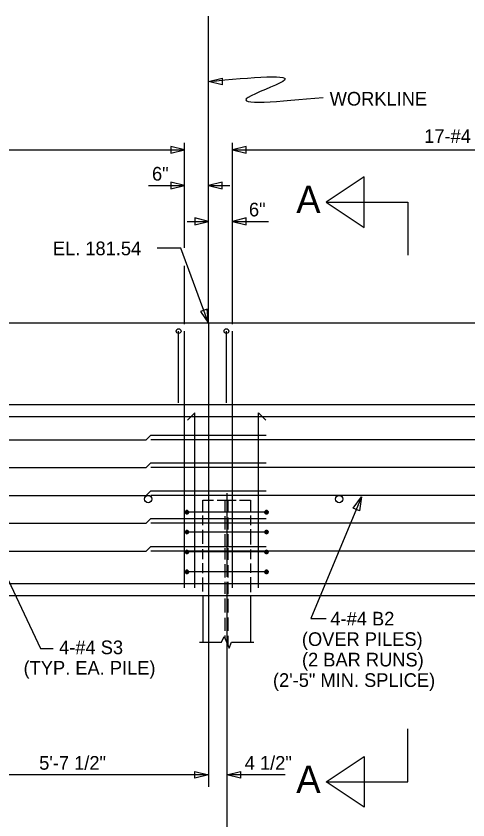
# Model space of a CAD drawing. Extents: x -41 to 191, y -168 to 6.
# Drawn here: x 28.81 to 38.27, y -40.55 to -23.72 of the extents above; entities that cross this region are included whole.
import ezdxf

# ---------------------------------------------------------------- set-up
doc = ezdxf.new("R2010")
doc.units = 0
for name, color, linetype in [('Arrowhead Terminators CELL', 7, 'Continuous'), ('Dimension Lines', 7, 'Continuous'), ('Mis -L- Lines', 7, 'Continuous'), ('Mis Object Lines', 7, 'Continuous'), ('Mis Object Lines Hidden', 7, 'Continuous'), ('Rebar Lines', 7, 'Continuous'), ('Rebar Lines CELL', 7, 'Continuous'), ('Text', 7, 'Continuous'), ('Title Text', 7, 'Continuous')]:
    doc.layers.add(name, color=color, linetype=linetype)

msp = doc.modelspace()

# ---------------------------------------------------------------- linework, layer by layer
at = {"layer": 'Arrowhead Terminators CELL'}
for points in [[(32.837, -25.09), (33.124, -25.018), (33.124, -25.161)], [(32.337, -26.52), (32.051, -26.448), (32.051, -26.591)], [(33.337, -26.52), (33.624, -26.591), (33.624, -26.448)], [(35.301, -27.616), (36.095, -28.145), (36.095, -27.087)], [(32.337, -27.27), (32.051, -27.198), (32.051, -27.341)], [(32.837, -27.27), (33.124, -27.341), (33.124, -27.198)], [(32.837, -28.02), (32.551, -27.948), (32.551, -28.091)], [(33.337, -28.02), (33.624, -28.091), (33.624, -27.948)], [(32.837, -30.152), (32.806, -29.858), (32.671, -29.908)], [(36.041, -33.79), (35.997, -34.082), (35.865, -34.027)], [(35.301, -39.757), (36.095, -39.228), (36.095, -40.286)], [(32.837, -39.61), (32.551, -39.681), (32.551, -39.538)], [(33.219, -39.61), (33.505, -39.538), (33.505, -39.681)]]:
    msp.add_lwpolyline(points, close=True, dxfattribs=at)
at = {"layer": 'Dimension Lines'}
for p, q in [((32.337, -28.571), (32.337, -26.377)), ((33.337, -30.175), (33.337, -26.377)), ((16.318, -26.52), (32.337, -26.52)), ((33.337, -26.52), (49.41, -26.52)), ((31.583, -27.27), (32.337, -27.27)), ((32.837, -27.27), (33.283, -27.27)), ((32.392, -28.02), (32.837, -28.02)), ((33.337, -28.02), (34.092, -28.02)), ((32.337, -30.175), (32.337, -28.947)), ((28.46, -35.153), (29.319, -36.963)), ((33.219, -35.86), (33.219, -42.157)), ((29.319, -36.963), (29.587, -36.963)), ((32.837, -39.61), (27.219, -39.61)), ((34.446, -39.61), (33.219, -39.61))]:
    msp.add_line(p, q, dxfattribs=at)
for points in [[(35.301, -27.616), (37.013, -27.616), (37.013, -28.727)], [(32.837, -30.152), (32.26, -28.581), (31.76, -28.581)], [(36.041, -33.79), (34.981, -36.334), (35.298, -36.334)], [(35.301, -39.757), (37.013, -39.757), (37.013, -38.646)]]:
    msp.add_lwpolyline(points, dxfattribs=at)
msp.add_spline([(32.837, -25.09), (34.392, -25.09), (33.667, -25.423), (35.236, -25.423)], degree=3, dxfattribs=at)
at = {"layer": 'Mis -L- Lines'}
for q in [(32.837, -23.72), (32.837, -39.86)]:
    msp.add_line((32.837, -30.152), q, dxfattribs=at)
at = {"layer": 'Mis Object Lines'}
for p, q in [((43.116, -30.152), (16.026, -30.152)), ((47.445, -35.86), (12.601, -35.86))]:
    msp.add_line(p, q, dxfattribs=at)
at = {"layer": 'Mis Object Lines Hidden'}
msp.add_line((49.619, -31.86), (12.601, -31.86), dxfattribs=at)
at = {"layer": 'Rebar Lines'}
for p, q in [((32.212, -31.818), (32.212, -30.318)), ((32.337, -35.693), (32.337, -30.318)), ((33.212, -31.818), (33.212, -30.318)), ((33.337, -35.693), (33.337, -30.318)), ((53.096, -32.111), (14.053, -32.111)), ((32.552, -32.027), (32.399, -32.18)), ((32.552, -35.693), (32.552, -32.027)), ((33.886, -35.693), (33.886, -32.027)), ((33.886, -32.027), (34.039, -32.18)), ((13.513, -32.591), (31.532, -32.591)), ((31.532, -32.591), (31.629, -32.494)), ((31.629, -32.494), (34.046, -32.494)), ((53.554, -32.591), (31.629, -32.591)), ((31.532, -33.174), (31.629, -33.077)), ((31.629, -33.077), (34.046, -33.077)), ((13.513, -33.174), (31.532, -33.174)), ((53.554, -33.174), (31.629, -33.174)), ((31.532, -33.757), (31.629, -33.661)), ((31.629, -33.661), (34.046, -33.661)), ((13.513, -33.757), (31.532, -33.757)), ((53.554, -33.757), (31.629, -33.757)), ((33.219, -33.709), (33.219, -35.465)), ((33.187, -34.103), (33.187, -33.86)), ((33.25, -34.108), (33.25, -33.86)), ((13.513, -34.34), (31.532, -34.34)), ((31.532, -34.34), (31.629, -34.244)), ((31.629, -34.244), (34.046, -34.244)), ((53.554, -34.34), (31.629, -34.34)), ((33.187, -34.474), (33.187, -34.196)), ((33.25, -34.474), (33.25, -34.219)), ((33.187, -34.817), (33.187, -34.567)), ((33.25, -34.829), (33.25, -34.567)), ((31.532, -34.924), (31.629, -34.827)), ((31.629, -34.827), (34.046, -34.827)), ((13.513, -34.924), (31.532, -34.924)), ((53.554, -34.924), (31.629, -34.924)), ((33.187, -35.103), (33.187, -34.86)), ((33.25, -35.108), (33.25, -34.86)), ((33.187, -35.474), (33.187, -35.196)), ((33.25, -35.474), (33.25, -35.219)), ((53.096, -35.61), (13.96, -35.61)), ((33.187, -35.817), (33.187, -35.567)), ((33.219, -35.57), (33.219, -35.86)), ((33.25, -35.829), (33.25, -35.567)), ((32.718, -35.877), (32.718, -36.829)), ((33.187, -36.212), (33.187, -35.916)), ((33.219, -35.93), (33.219, -37.136)), ((33.25, -36.212), (33.25, -35.922)), ((33.72, -35.877), (33.72, -36.829)), ((33.187, -36.595), (33.187, -36.322)), ((33.25, -36.595), (33.25, -36.317)), ((33.187, -36.763), (33.187, -36.689)), ((33.25, -36.913), (33.25, -36.7))]:
    msp.add_line(p, q, dxfattribs=at)
for points in [[(32.718, -34.094), (32.718, -33.86), (32.941, -33.86)], [(33.017, -33.86), (33.416, -33.86)], [(33.486, -33.86), (33.718, -33.86), (33.718, -34.106)], [(32.718, -34.384), (32.718, -34.176)], [(33.718, -34.182), (33.718, -34.381)], [(32.718, -34.771), (32.718, -34.48)], [(33.718, -34.467), (33.718, -34.787)], [(32.718, -35.094), (32.718, -34.886)], [(33.718, -34.892), (33.718, -35.091)], [(32.718, -35.384), (32.718, -35.176)], [(33.718, -35.182), (33.718, -35.381)], [(32.718, -35.771), (32.718, -35.48)], [(33.718, -35.467), (33.718, -35.787)], [(32.649, -36.829), (33.111, -36.829), (33.165, -36.71), (33.267, -36.954), (33.319, -36.829), (33.786, -36.829)]]:
    msp.add_lwpolyline(points, dxfattribs=at)
for centre in [(32.212, -30.318), (33.212, -30.318)]:
    msp.add_circle(centre, 0.0495, dxfattribs=at)
at = {"layer": 'Rebar Lines CELL'}
for p, q in [((34.052, -34.11), (32.386, -34.11)), ((34.052, -34.527), (32.386, -34.527)), ((34.052, -34.943), (32.386, -34.943)), ((34.052, -35.36), (32.386, -35.36))]:
    msp.add_line(p, q, dxfattribs=at)
for points in [[(32.386, -34.075), (32.372, -34.077), (32.361, -34.085), (32.353, -34.096), (32.35, -34.11), (32.353, -34.123), (32.361, -34.135), (32.372, -34.142), (32.386, -34.145), (32.399, -34.142), (32.41, -34.135), (32.418, -34.123), (32.421, -34.11), (32.418, -34.096), (32.411, -34.085), (32.399, -34.077), (32.386, -34.075), (32.386, -34.11), (32.386, -34.145), (32.372, -34.142), (32.386, -34.11), (32.361, -34.135), (32.353, -34.123), (32.386, -34.11), (32.35, -34.11), (32.353, -34.096), (32.386, -34.11), (32.361, -34.085), (32.372, -34.077), (32.386, -34.11), (32.399, -34.077), (32.411, -34.085), (32.386, -34.11), (32.418, -34.096), (32.421, -34.11), (32.386, -34.11), (32.418, -34.123), (32.41, -34.135), (32.386, -34.11), (32.399, -34.142)], [(34.052, -34.075), (34.039, -34.077), (34.027, -34.085), (34.02, -34.096), (34.017, -34.11), (34.02, -34.123), (34.027, -34.135), (34.039, -34.142), (34.052, -34.145), (34.066, -34.142), (34.077, -34.135), (34.085, -34.123), (34.088, -34.11), (34.085, -34.096), (34.077, -34.085), (34.066, -34.077), (34.052, -34.075), (34.052, -34.11), (34.052, -34.145), (34.039, -34.142), (34.052, -34.11), (34.027, -34.135), (34.02, -34.123), (34.052, -34.11), (34.017, -34.11), (34.02, -34.096), (34.052, -34.11), (34.027, -34.085), (34.039, -34.077), (34.052, -34.11), (34.066, -34.077), (34.077, -34.085), (34.052, -34.11), (34.085, -34.096), (34.088, -34.11), (34.052, -34.11), (34.085, -34.123), (34.077, -34.135), (34.052, -34.11), (34.066, -34.142)], [(32.386, -34.491), (32.372, -34.494), (32.361, -34.502), (32.353, -34.513), (32.35, -34.527), (32.353, -34.54), (32.361, -34.551), (32.372, -34.559), (32.386, -34.562), (32.399, -34.559), (32.41, -34.551), (32.418, -34.54), (32.421, -34.527), (32.418, -34.513), (32.411, -34.502), (32.399, -34.494), (32.386, -34.491), (32.386, -34.527), (32.386, -34.562), (32.372, -34.559), (32.386, -34.527), (32.361, -34.551), (32.353, -34.54), (32.386, -34.527), (32.35, -34.527), (32.353, -34.513), (32.386, -34.527), (32.361, -34.502), (32.372, -34.494), (32.386, -34.527), (32.399, -34.494), (32.411, -34.502), (32.386, -34.527), (32.418, -34.513), (32.421, -34.527), (32.386, -34.527), (32.418, -34.54), (32.41, -34.551), (32.386, -34.527), (32.399, -34.559)], [(34.052, -34.491), (34.039, -34.494), (34.027, -34.502), (34.02, -34.513), (34.017, -34.527), (34.02, -34.54), (34.027, -34.551), (34.039, -34.559), (34.052, -34.562), (34.066, -34.559), (34.077, -34.551), (34.085, -34.54), (34.088, -34.527), (34.085, -34.513), (34.077, -34.502), (34.066, -34.494), (34.052, -34.491), (34.052, -34.527), (34.052, -34.562), (34.039, -34.559), (34.052, -34.527), (34.027, -34.551), (34.02, -34.54), (34.052, -34.527), (34.017, -34.527), (34.02, -34.513), (34.052, -34.527), (34.027, -34.502), (34.039, -34.494), (34.052, -34.527), (34.066, -34.494), (34.077, -34.502), (34.052, -34.527), (34.085, -34.513), (34.088, -34.527), (34.052, -34.527), (34.085, -34.54), (34.077, -34.551), (34.052, -34.527), (34.066, -34.559)], [(32.386, -34.908), (32.372, -34.911), (32.361, -34.918), (32.353, -34.93), (32.35, -34.943), (32.353, -34.957), (32.361, -34.968), (32.372, -34.976), (32.386, -34.978), (32.399, -34.976), (32.41, -34.968), (32.418, -34.957), (32.421, -34.943), (32.418, -34.93), (32.411, -34.918), (32.399, -34.911), (32.386, -34.908), (32.386, -34.943), (32.386, -34.978), (32.372, -34.976), (32.386, -34.943), (32.361, -34.968), (32.353, -34.957), (32.386, -34.943), (32.35, -34.943), (32.353, -34.93), (32.386, -34.943), (32.361, -34.918), (32.372, -34.911), (32.386, -34.943), (32.399, -34.911), (32.411, -34.918), (32.386, -34.943), (32.418, -34.93), (32.421, -34.943), (32.386, -34.943), (32.418, -34.957), (32.41, -34.968), (32.386, -34.943), (32.399, -34.976)], [(34.052, -34.908), (34.039, -34.911), (34.027, -34.918), (34.02, -34.93), (34.017, -34.943), (34.02, -34.957), (34.027, -34.968), (34.039, -34.976), (34.052, -34.978), (34.066, -34.976), (34.077, -34.968), (34.085, -34.957), (34.088, -34.943), (34.085, -34.93), (34.077, -34.918), (34.066, -34.911), (34.052, -34.908), (34.052, -34.943), (34.052, -34.978), (34.039, -34.976), (34.052, -34.943), (34.027, -34.968), (34.02, -34.957), (34.052, -34.943), (34.017, -34.943), (34.02, -34.93), (34.052, -34.943), (34.027, -34.918), (34.039, -34.911), (34.052, -34.943), (34.066, -34.911), (34.077, -34.918), (34.052, -34.943), (34.085, -34.93), (34.088, -34.943), (34.052, -34.943), (34.085, -34.957), (34.077, -34.968), (34.052, -34.943), (34.066, -34.976)], [(32.386, -35.325), (32.372, -35.327), (32.361, -35.335), (32.353, -35.346), (32.35, -35.36), (32.353, -35.373), (32.361, -35.385), (32.372, -35.392), (32.386, -35.395), (32.399, -35.392), (32.41, -35.385), (32.418, -35.373), (32.421, -35.36), (32.418, -35.346), (32.411, -35.335), (32.399, -35.327), (32.386, -35.325), (32.386, -35.36), (32.386, -35.395), (32.372, -35.392), (32.386, -35.36), (32.361, -35.385), (32.353, -35.373), (32.386, -35.36), (32.35, -35.36), (32.353, -35.346), (32.386, -35.36), (32.361, -35.335), (32.372, -35.327), (32.386, -35.36), (32.399, -35.327), (32.411, -35.335), (32.386, -35.36), (32.418, -35.346), (32.421, -35.36), (32.386, -35.36), (32.418, -35.373), (32.41, -35.385), (32.386, -35.36), (32.399, -35.392)], [(34.052, -35.325), (34.039, -35.327), (34.027, -35.335), (34.02, -35.346), (34.017, -35.36), (34.02, -35.373), (34.027, -35.385), (34.039, -35.392), (34.052, -35.395), (34.066, -35.392), (34.077, -35.385), (34.085, -35.373), (34.088, -35.36), (34.085, -35.346), (34.077, -35.335), (34.066, -35.327), (34.052, -35.325), (34.052, -35.36), (34.052, -35.395), (34.039, -35.392), (34.052, -35.36), (34.027, -35.385), (34.02, -35.373), (34.052, -35.36), (34.017, -35.36), (34.02, -35.346), (34.052, -35.36), (34.027, -35.335), (34.039, -35.327), (34.052, -35.36), (34.066, -35.327), (34.077, -35.335), (34.052, -35.36), (34.085, -35.346), (34.088, -35.36), (34.052, -35.36), (34.085, -35.373), (34.077, -35.385), (34.052, -35.36), (34.066, -35.392)]]:
    msp.add_lwpolyline(points, dxfattribs=at)
for centre in [(31.574, -33.834), (35.574, -33.834)]:
    msp.add_circle(centre, 0.0773, dxfattribs=at)

# ---------------------------------------------------------------- texts
at = {"layer": 'Text'}
for s, p in [('WORKLINE', (35.375, -25.594)), ('17-#4 V2 @ 1\'-0" CTS. (EA. FACE)', (37.355, -26.377)), ('6"', (31.654, -27.165)), ('6"', (33.684, -27.915)), ('EL. 181.54', (29.577, -28.729)), ('4-#4 B2', (35.39, -36.482)), ('(OVER PILES)', (34.793, -36.911)), ('4-#4 S3', (29.708, -37.083)), ('(2 BAR RUNS)', (34.795, -37.34)), ('(TYP. EA. PILE)', (28.964, -37.512)), ('(2\'-5" MIN. SPLICE)', (34.187, -37.769)), ('5\'-7 1/2"', (29.291, -39.503)), ('4 1/2"', (33.596, -39.503))]:
    msp.add_text(s, height=0.286, dxfattribs=at).set_placement(p)
at = {"layer": 'Title Text'}
for p in [(34.675, -27.847), (34.675, -39.989)]:
    msp.add_text('A', height=0.572, rotation=0, dxfattribs=at).set_placement(p)

doc.saveas('drawing.dxf')
